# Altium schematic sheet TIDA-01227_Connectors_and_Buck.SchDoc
size A4; Date: Not shown in title block; ApprovedBy: Not shown in title block; CheckedBy: Not shown in title block; Author: Not shown in title block; CompanyName: Not shown in title block; Engineer: Not shown in title block; Organization: Not shown in title block; Address1: Not shown in title block; Address2: Not shown in title block; Address3: Not shown in title block; Address4: Not shown in title block; DocumentNumber: 2; Revision: Use project parameter SCH_Rev; SheetNumber: 2; SheetTotal: 4; PageSetup: Record=PageOptions¦CenterHorizontal=True¦CenterVertical=True¦PrintScale=1.00¦XCorrection=1.00¦YCorrection=1.00¦PrintKind=0¦BorderSize=5000000¦LeftOffset=0¦BottomOffset=0¦Orientation=2¦PaperLength=1000¦PaperWidth=1000¦Scale=100¦PaperSource=15¦PrintQuality=600¦MediaType=1¦DitherType=10¦PaperKind=Letter¦PrintScaleMode=1
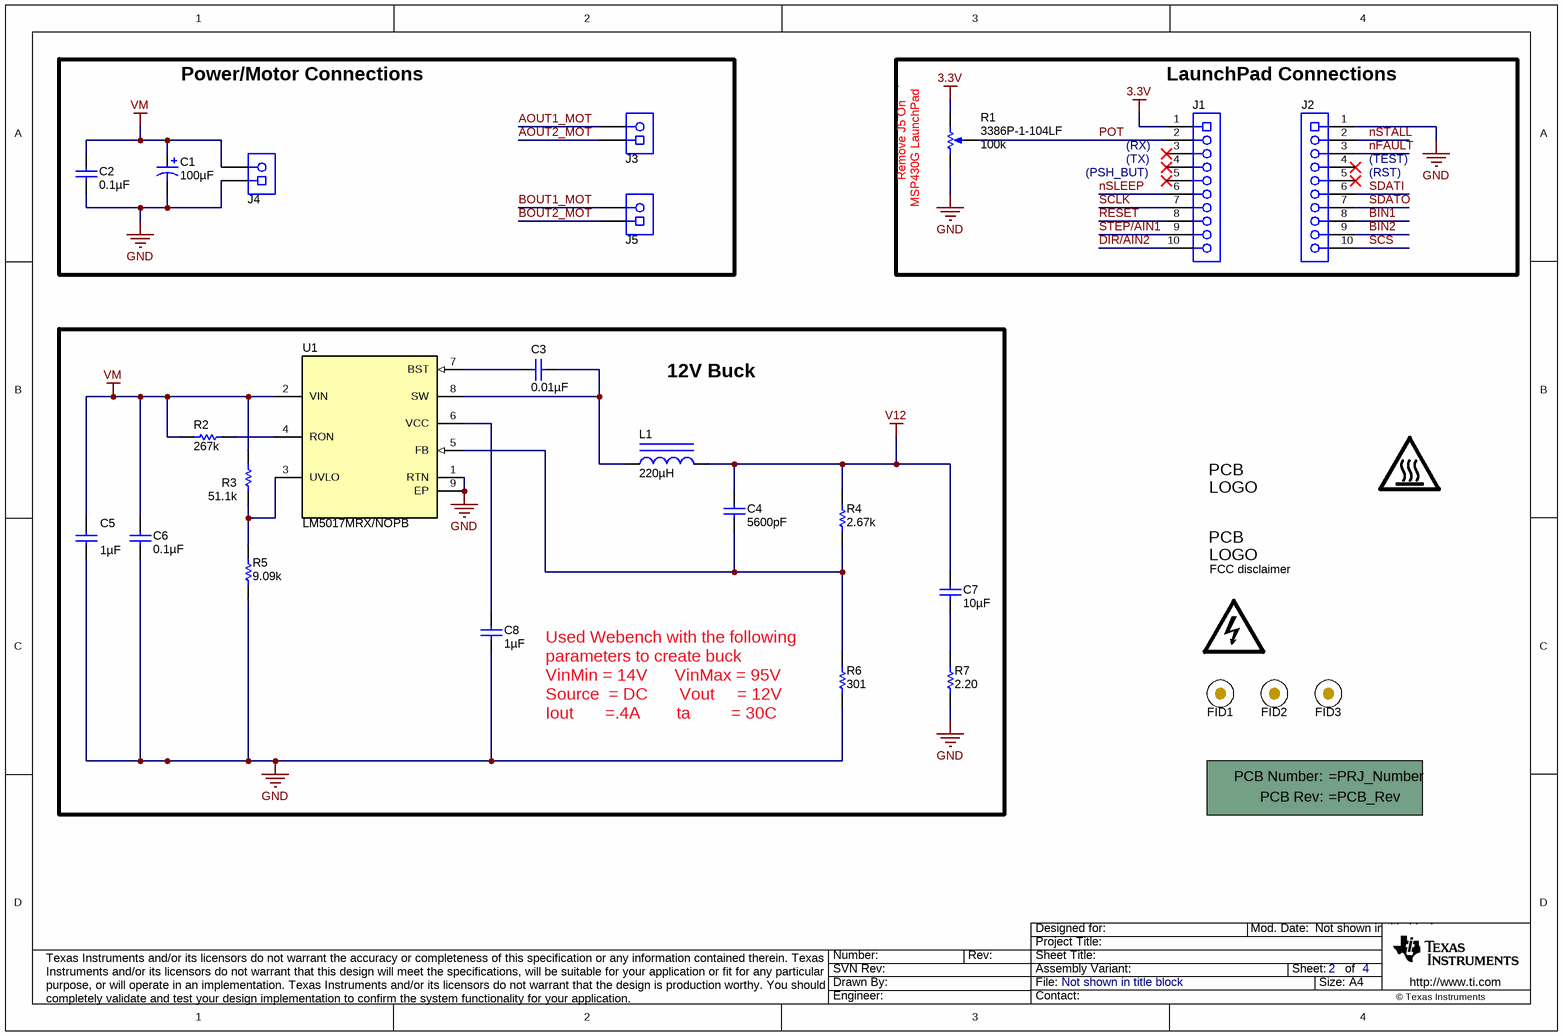
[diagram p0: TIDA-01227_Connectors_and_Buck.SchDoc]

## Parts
!PCB1  Printed Circuit Board  (value not drawn)  (mechanical)
C1  ValueDisplayed: 100µF  [NHG_1000x2000]  (hidden comment: ECA-2AHG101)
C2  ValueDisplayed: 0.1µF  [0805L]  (hidden comment: C0805C104K1RACTU)
C3  ValueDisplayed: 0.01µF  [0402L]  (hidden comment: 885012205031)
C4  ValueDisplayed: 5600pF  [0603L]  (hidden comment: 06031C562JAT2A)
C5  ValueDisplayed: 1µF  [1206L]  (hidden comment: C3216X7R2A105M160AA)
C6  ValueDisplayed: 0.1µF  [0805L]  (hidden comment: C2012X7R2A104K125AA)
C7  ValueDisplayed: 10µF  [0805L]  (hidden comment: CL21A106KAFN3NE)
C8  ValueDisplayed: 1µF  [0805L]  (hidden comment: GRM21BR71H105KA12L)
FID1  Fiducial  [Fiducial10-20]  (value not drawn)
FID2  Fiducial  [Fiducial10-20]  (value not drawn)
FID3  Fiducial  [Fiducial10-20]  (value not drawn)
J1  61301011821  [Wurth_61301011821]  (value not drawn)
J2  61301011821  [Wurth_61301011821]  (value not drawn)
J3  691 101 710 002  [Wurth_691101710002]  (value not drawn)
J4  691 101 710 002  [Wurth_691101710002]  (value not drawn)
J5  691 101 710 002  [Wurth_691101710002]  (value not drawn)
L1  ValueDisplayed: 220µH  [WE-PD_1280]  (hidden comment: 744770222)
Logo1  EU RoHS Exempt Logo  [EURoHS_Exempt_60mil]  (value not drawn)  (no BOM)
Logo2  FCC disclaimer  [FCC_disclaimer_stacked]  (no BOM)
LOGO3  DANGER HIGH VOLTAGE  [IEC_HighVoltage_Small]  (value not drawn)  (no BOM)
LOGO4  CAUTION HOT SURFACE  [IEC_HotSurface_Small]  (value not drawn)  (no BOM)
R1  3386P-1-104LF  value 100k  [BOURNS_3386P]
R2  ValueDisplayed: 267k  [0402L]  (hidden comment: CRCW0402267KFKED)
R3  ValueDisplayed: 51.1k  [0402L]  (hidden comment: CRCW040251K1FKED)
R4  ValueDisplayed: 2.67k  [0402L]  (hidden comment: CRCW04022K67FKED)
R5  ValueDisplayed: 9.09k  [0402L]  (hidden comment: CRCW04029K09FKED)
R6  ValueDisplayed: 301  [0402L]  (hidden comment: CRCW0402301RFKED)
R7  ValueDisplayed: 2.20  [0805L]  (hidden comment: ERJ-6RQF2R2V)
U1  LM5017MRX/NOPB  [DDA0008B_N]

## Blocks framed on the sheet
Power/Motor Connections: C1 C2 J3-J5
12V Buck: C3-C8 L1 R2-R7 U1

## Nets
3.3V: J1.1 R1.3(CW)
GND: C1.2(-) C2.2 C5.2 C6.2 C8.2 J2.1 J4.1 R1.1(CCW) R5.1 R6.1 R7.1 U1.1(RTN) U1.9(EP)
V12: C4.1 C7.1 L1.2 R4.2
VM: C1.1(+) C2.1 C5.1 C6.1 J4.2 R2.1 R3.2 U1.2(VIN)
AOUT1_MOT: J3.2
AOUT2_MOT: J3.1
BIN1: J2.8
BIN2: J2.9
BOUT1_MOT: J5.2
BOUT2_MOT: J5.1
DIR/AIN2: J1.10
nFAULT: J2.3
nSLEEP: J1.6
nSTALL: J2.2
POT: J1.2 R1.2(WIPER)
RESET: J1.8
SCLK: J1.7
SCS: J2.10
SDATI: J2.6
SDATO: J2.7
STEP/AIN1: J1.9
NetC3_1: C3.1 U1.7(BST)
NetC3_2: C3.2 L1.1 U1.8(SW)
NetC4_2: C4.2 R4.1 R6.2 U1.5(FB)
NetC7_2: C7.2 R7.2
NetC8_1: C8.1 U1.6(VCC)
NetR2_2: R2.2 U1.4(RON)
NetR3_1: R3.1 R5.2 U1.3(UVLO)

Not connected (* = marked no-connect by the designer): J1 3* 4* 5*; J2 4* 5*

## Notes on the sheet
- LaunchPad Connections
- (near R1) Remove J5 On
- (near J1) (PSH_BUT)
- (near J1) (RX)
- (near J1) (TX)
- (near J2) (TEST)
- (near J2) (RST)
- (near R1) MSP430G LaunchPad
- (near R6) Used Webench with the following parameters to create buck
  VinMin = 14V      VinMax = 95V
  Source  = DC       Vout     = 12V
  Iout       =.4A        ta         = 30C

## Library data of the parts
!PCB1 = PCB: Manufacturer: Any; SymbolCreator: a0412235
C1 = ECA-2AHG101: CAP, AL, 100 µF, 100 V, +/- 20%, TH; Manufacturer: Panasonic; Polarized: Y; CompType: Capacitor; Value: 100uF; U/M: EA; Cap_F: 0.0001; Tolerance_%: 20; Value1: Unknown; VDC_V: 100; Value2: 100V; IRMS_A: 0.265; TaMin_C: -55; TaMax_C: 105; Cap_Case: 10x20mm; AEC Category: Q200
C2 = C0805C104K1RACTU: CAP, CERM, 0.1 µF, 100 V, +/- 10%, X7R, 0805; Manufacturer: Kemet; Polarized: N; CompType: Capacitor; Value: 0.1uF; U/M: EA; Cap_F: 0.0000001; Tolerance_%: 10; ESR_ohm: 0.064; Value1: 0.064 ohm; VDC_V: 100; Value2: 100V; IRMS_A: 1.64; TaMin_C: -55; TaMax_C: 125; Cap_Case: 0805; SizeArea_mm2: 2.5; SizeAreaWB_mm2: 6.75; SizeX_mm: 2; SizeY_mm: 1.25; SizeZ_mm: 1.45; AEC Category: Q200
C3 = 885012205031: CAP, CERM, 0.01 µF, 16 V, +/- 10%, X7R, 0402; Manufacturer: Wurth Elektronik; Polarized: N; CompType: Capacitor; Value: 0.01uF; U/M: EA; Cap_F: 0.00000001; Tolerance_%: 10; Value1: Unknown; VDC_V: 16; Value2: 16V; TaMin_C: -55; TaMax_C: 125; Cap_Case: 0402; AEC Category: Q200
C4 = 06031C562JAT2A: CAP, CERM, 5600 pF, 100 V, +/- 5%, X7R, 0603; Manufacturer: AVX; Polarized: N; CompType: Capacitor; Value: 5600pF; U/M: EA; Cap_F: 0.0000000056; Tolerance_%: 5; ESR_ohm: 0.125; Value1: 0.125 ohm; VDC_V: 100; Value2: 100V; TaMin_C: -55; TaMax_C: 125; Cap_Case: 0603; SizeArea_mm2: 1.28; SizeAreaWB_mm2: 4.68; SizeX_mm: 1.6; SizeY_mm: 0.8; SizeZ_mm: 1; AEC Category: Q200
C5 = C3216X7R2A105M160AA: CAP, CERM, 1 µF, 100 V, +/- 20%, X7R, 1206; Manufacturer: TDK; Polarized: N; CompType: Capacitor; Value: 1uF; U/M: EA; Cap_F: 0.000001; Tolerance_%: 20; Value1: Unknown; VDC_V: 100; Value2: 100V; TaMin_C: -55; TaMax_C: 125; Cap_Case: 1206
C6 = C2012X7R2A104K125AA: CAP, CERM, 0.1 µF, 100 V, +/- 10%, X7R, 0805; Manufacturer: TDK; Polarized: N; CompType: Capacitor; Value: 0.1uF; U/M: EA; Cap_F: 0.0000001; Tolerance_%: 10; ESR_ohm: 0.0158; Value1: 0.0158 ohm; VDC_V: 100; Value2: 100V; TaMin_C: -55; TaMax_C: 125; Cap_Case: 0805; AEC Category: Q200
C7 = CL21A106KAFN3NE: CAP, CERM, 10 µF, 25 V, +/- 10%, X5R, 0805; Manufacturer: Samsung Electro-Mechanics; Polarized: N; CompType: Capacitor; Value: 10uF; U/M: EA; Cap_F: 0.00001; Tolerance_%: 10; Value1: Unknown; VDC_V: 25; Value2: 25V; TaMin_C: -55; TaMax_C: 85; Cap_Case: 0805; AEC Category: Q200; SizeArea_mm2: 2.5; SizeAreaWB_mm2: 6.75; SizeX_mm: 2; SizeY_mm: 1.25; SizeZ_mm: 1.45
C8 = GRM21BR71H105KA12L: CAP, CERM, 1 µF, 50 V, +/- 10%, X7R, 0805; Manufacturer: MuRata; Polarized: N; CompType: Capacitor; Value: 1uF; U/M: EA; Cap_F: 0.000001; Tolerance_%: 10; Value1: Unknown; VDC_V: 50; Value2: 50V; TaMin_C: -55; TaMax_C: 125; Cap_Case: 0805; SizeArea_mm2: 2.5; SizeAreaWB_mm2: 6.75; SizeX_mm: 2; SizeY_mm: 1.25; SizeZ_mm: 1.45; AEC Category: Q200
FID1-FID3 = Fiducial: Fiducial mark.  There is nothing to buy or mount.; SymbolCreator: codlsc
J1 J2 = 61301011821: Receptacle, 2.54mm, 10x1, Gold, TH; Manufacturer: Wurth Elektronik; SymbolCreator: a0411947; U/M: EA
J3-J5 = 691 101 710 002: Terminal Block, 5 mm, 2x1, Tin, TH; Manufacturer: Wurth Elektronik; SymbolCreator: a0412235; U/M: EA
L1 = 744770222: Inductor, Shielded Drum Core, Ferrite, 220 µH, 1.3 A, 0.39 ohm, SMD; Manufacturer: Wurth Elektronik; Value: 220uH; Ind_H: 220.0E-6; Imax_A: 1.3; Irms: 1.3A @ 40C rise; Isat: 1.49A @ 10% inductance drop; DCR_ohm: 0.39; Value2: 1.3A; AEC Category: Q200
Logo1 = EURoHS_Exempt: SymbolCreator: a0412235
Logo2 = FCC_disclaimer: SymbolCreator: codlsc
LOGO3 = IEC_HighVoltage: IEC 61010-1 High Voltage Warning; SymbolCreator: a0412235
LOGO4 = IEC_HotSurface: IEC 61010-1 Hot Surface Warning; SymbolCreator: a0412235
R1 = 3386P-1-104LF: TRIMMER, 100k ohm, 0.5W, TH; Manufacturer: Bourns; Sim Note: Enter the Resistance value and the set point into parameter fields.; SymbolCreator: a0412235
R2 = CRCW0402267KFKED: RES, 267 k, 1%, 0.063 W, 0402; Manufacturer: Vishay-Dale; CompType: Resistor; Value: 267k; Res_ohm: 267000; Tolerance_%: 1; Power_W: 0.063; Value2: 0.063W; VDC_V: 50; TempCo: 100 ppm/C; EIA_Code: E96; U/M: EA; SizeArea_mm2: 0.5; SizeZ_mm: 0.6; AEC Category: Q200
R3 = CRCW040251K1FKED: RES, 51.1 k, 1%, 0.063 W, 0402; Manufacturer: Vishay-Dale; CompType: Resistor; Value: 51.1k; Res_ohm: 51100; Value_Code: 51k1; Tolerance_%: 1; Power_W: 0.063; Value2: 0.063W; VDC_V: 50; TempCo: 100 ppm/C; EIA_Code: E96; U/M: EA; SizeArea_mm2: 0.5; SizeZ_mm: 0.6; AEC Category: Q200
R4 = CRCW04022K67FKED: RES, 2.67 k, 1%, 0.063 W, 0402; Manufacturer: Vishay-Dale; CompType: Resistor; Value: 2.67k; Res_ohm: 2670; Value_Code: 2k67; Tolerance_%: 1; Power_W: 0.063; Value2: 0.063W; VDC_V: 50; TempCo: 100 ppm/C; EIA_Code: E96; U/M: EA; AEC Category: Q200; SizeArea_mm2: 0.5; SizeZ_mm: 0.6
R5 = CRCW04029K09FKED: RES, 9.09 k, 1%, 0.063 W, 0402; Manufacturer: Vishay-Dale; CompType: Resistor; Value: 9.09k; Res_ohm: 9090; Value_Code: 9k09; Tolerance_%: 1; Power_W: 0.063; Value2: 0.063W; VDC_V: 50; TempCo: 100 ppm/C; EIA_Code: E96; U/M: EA; AEC Category: Q200; SizeArea_mm2: 0.5; SizeZ_mm: 0.6
R6 = CRCW0402301RFKED: RES, 301, 1%, 0.063 W, 0402; Manufacturer: Vishay-Dale; CompType: Resistor; Value: 301; Value_Code: 301R; Tolerance_%: 1; Power_W: 0.063; Value2: 0.063W; VDC_V: 50; TempCo: 100 ppm/C; EIA_Code: E96; U/M: EA; AEC Category: Q200; SizeArea_mm2: 0.5; SizeZ_mm: 0.6
R7 = ERJ-6RQF2R2V: RES, 2.20, 1%, 0.125 W, 0805; Manufacturer: Panasonic; CompType: Resistor; Value: 2.20; Res_ohm: 2.2; Value_Code: 2R20; Tolerance_%: 1; Power_W: 0.125; Value2: 0.125W; TempCo: 200 ppm/C; U/M: EA; SizeArea_mm2: 2.5; SizeX_mm: 2; SizeY_mm: 1.25; SizeZ_mm: 1.45; AEC Category: Q200
U1 = LM5017MRX/NOPB: 100V, 600mA Constant On-Time Synchronous Buck Regulator, DDA0008B; Alternate PartNumber: LM5017MR/NOPB; Manufacturer: Texas Instruments; SymbolCreator: a0412235; SizeArea_mm2: 31; SizeAreaWB_mm2: 57.4; SizeX_mm: 5; SizeY_mm: 6.2; SizeZ_mm: 1.7; CompType: IC; U/M: EA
